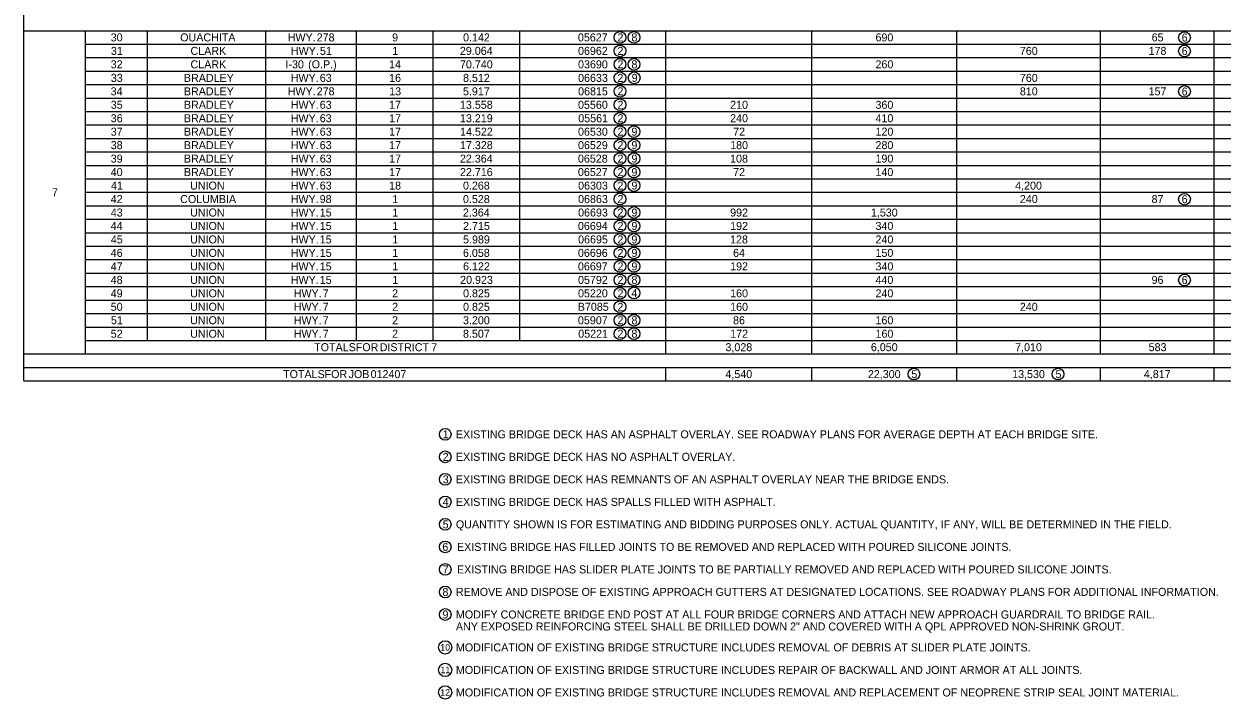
# Model space of a CAD drawing. Extents: x 16 to 1228740, y 11 to 152440.
# Drawn here: x 15.863 to 17.42, y 10.807 to 11.685 of the extents above; entities that cross this region are included whole.
import ezdxf

# ---------------------------------------------------------------- set-up
doc = ezdxf.new("R2010")
doc.units = 0
doc.layers.add('B_Text', color=7, linetype='Continuous')
doc.layers.add('Default', color=7, linetype='Continuous')

msp = doc.modelspace()

# ---------------------------------------------------------------- linework, layer by layer
at = {"layer": 'B_Text'}
for centre, radius in [((16.6381, 11.6677), 0.00762), ((16.6563, 11.6677), 0.00762), ((17.3717, 11.6675), 0.00762), ((16.6381, 11.6502), 0.00762), ((17.3717, 11.65), 0.00762), ((16.6381, 11.6327), 0.00762), ((16.6563, 11.6327), 0.00762), ((16.6381, 11.6151), 0.00762), ((16.6565, 11.6151), 0.00762), ((16.6381, 11.5976), 0.00762), ((17.3717, 11.5974), 0.00762), ((16.6381, 11.5801), 0.00762), ((16.6381, 11.5626), 0.00762), ((16.6381, 11.5451), 0.00762), ((16.6563, 11.5451), 0.00762), ((16.6381, 11.5276), 0.00762), ((16.6563, 11.5276), 0.00762), ((16.6381, 11.5101), 0.00762), ((16.6563, 11.5101), 0.00762), ((16.6381, 11.4926), 0.00762), ((16.6563, 11.4926), 0.00762), ((16.6381, 11.475), 0.00762), ((16.6563, 11.475), 0.00762), ((16.6381, 11.4575), 0.00762), ((17.3717, 11.4573), 0.00762), ((16.6381, 11.44), 0.00762), ((16.6563, 11.44), 0.00762), ((16.6381, 11.4225), 0.00762), ((16.6563, 11.4225), 0.00762), ((16.6381, 11.405), 0.00762), ((16.6563, 11.405), 0.00762), ((16.6381, 11.3875), 0.00762), ((16.6563, 11.3875), 0.00762), ((16.6381, 11.37), 0.00762), ((16.6563, 11.37), 0.00762), ((16.6381, 11.3524), 0.00762), ((16.6563, 11.3524), 0.00762), ((17.3717, 11.3522), 0.00762), ((16.6381, 11.3349), 0.00762), ((16.6563, 11.3353), 0.00762), ((16.6381, 11.3174), 0.00762), ((16.6381, 11.2999), 0.00762), ((16.6563, 11.2999), 0.00762), ((16.6381, 11.2824), 0.00762), ((16.6563, 11.2824), 0.00762), ((17.02, 11.2299), 0.00762), ((17.2073, 11.2299), 0.00762), ((16.4109, 11.1516), 0.00762), ((16.4109, 11.1223), 0.00762), ((16.4109, 11.093), 0.00762), ((16.4109, 11.0637), 0.00762), ((16.4109, 11.0345), 0.00762), ((16.4109, 11.0052), 0.00762), ((16.4109, 10.9759), 0.00762), ((16.4109, 10.9466), 0.00762), ((16.4109, 10.9173), 0.00762), ((16.4109, 10.8745), 0.0086), ((16.4109, 10.8452), 0.0086), ((16.4109, 10.816), 0.0086)]:
    msp.add_circle(centre, radius, dxfattribs=at)
at = {"layer": 'Default'}
for p, q in [((15.8634, 11.2211), (15.8634, 12.342)), ((15.8634, 11.6764), (17.9605, 11.6764)), ((15.9436, 11.2561), (15.9436, 11.6764)), ((16.0238, 11.2736), (16.0238, 11.6764)), ((16.1778, 11.2736), (16.1778, 11.6764)), ((16.2958, 11.2736), (16.2958, 11.6764)), ((16.3953, 11.2736), (16.3953, 11.6764)), ((16.5078, 11.2736), (16.5078, 11.6764)), ((16.6976, 11.2561), (16.6976, 11.6764)), ((16.8875, 11.2561), (16.8875, 11.6764)), ((17.0756, 11.2561), (17.0756, 11.6764)), ((17.2627, 11.2561), (17.2627, 11.6764)), ((17.4102, 11.2561), (17.4102, 11.6764)), ((15.9436, 11.6589), (17.9605, 11.6589)), ((16.8875, 11.6414), (16.8875, 11.6589)), ((17.0756, 11.6414), (17.0756, 11.6589)), ((15.9436, 11.6414), (17.9605, 11.6414)), ((16.8875, 11.6414), (17.0756, 11.6414)), ((17.0756, 11.6414), (17.9605, 11.6414)), ((15.9436, 11.6239), (17.9605, 11.6239)), ((15.9436, 11.6064), (17.9605, 11.6064)), ((15.9436, 11.5889), (17.9605, 11.5889)), ((15.9436, 11.5714), (17.9605, 11.5714)), ((15.9436, 11.5539), (17.9605, 11.5539)), ((15.9436, 11.5363), (17.9605, 11.5363)), ((15.9436, 11.5188), (17.9605, 11.5188)), ((15.9436, 11.5013), (17.9605, 11.5013)), ((15.9436, 11.4838), (17.9605, 11.4838)), ((15.9436, 11.4663), (17.9605, 11.4663)), ((15.9436, 11.4488), (17.9605, 11.4488)), ((15.9436, 11.4313), (17.9605, 11.4313)), ((15.9436, 11.4137), (17.9605, 11.4137)), ((15.9436, 11.3962), (17.9605, 11.3962)), ((15.9436, 11.3787), (17.9605, 11.3787)), ((15.9436, 11.3612), (17.9605, 11.3612)), ((15.9436, 11.3437), (17.9605, 11.3437)), ((15.9436, 11.3262), (17.9605, 11.3262)), ((15.9436, 11.3087), (17.9605, 11.3087)), ((15.9436, 11.2911), (17.9605, 11.2911)), ((15.9436, 11.2736), (17.9605, 11.2736)), ((15.8634, 11.2561), (17.9605, 11.2561)), ((15.8634, 11.2386), (17.9605, 11.2386)), ((16.6976, 11.2211), (16.6976, 11.2386)), ((16.8875, 11.2211), (16.8875, 11.2386)), ((17.0756, 11.2211), (17.0756, 11.2386)), ((17.2627, 11.2211), (17.2627, 11.2386)), ((17.4102, 11.2211), (17.4102, 11.2386)), ((15.8634, 11.2211), (17.9605, 11.2211))]:
    msp.add_line(p, q, dxfattribs=at)

# ---------------------------------------------------------------- texts
at = {"layer": 'B_Text'}
for s, height, p in [('2', 0.0104, (16.6348, 11.6625)), ('8', 0.0104, (16.6529, 11.6625)), ('6', 0.0104, (17.368, 11.6623)), ('2', 0.0104, (16.6348, 11.645)), ('6', 0.0104, (17.368, 11.6448)), ('2', 0.0104, (16.6348, 11.6275)), ('8', 0.0104, (16.6529, 11.6275)), ('2', 0.0104, (16.6348, 11.6099)), ('9', 0.0104, (16.6532, 11.6099)), ('2', 0.0104, (16.6348, 11.5924)), ('6', 0.0104, (17.368, 11.5922)), ('2', 0.0104, (16.6348, 11.5749)), ('2', 0.0104, (16.6348, 11.5574)), ('2', 0.0104, (16.6348, 11.5399)), ('9', 0.0104, (16.6529, 11.5399)), ('2', 0.0104, (16.6348, 11.5224)), ('9', 0.0104, (16.6529, 11.5224)), ('2', 0.0104, (16.6348, 11.5049)), ('9', 0.0104, (16.6529, 11.5049)), ('2', 0.0104, (16.6348, 11.4873)), ('9', 0.0104, (16.6529, 11.4873)), ('2', 0.0104, (16.6348, 11.4698)), ('9', 0.0104, (16.6529, 11.4698)), ('2', 0.0104, (16.6348, 11.4523)), ('6', 0.0104, (17.368, 11.4521)), ('2', 0.0104, (16.6348, 11.4348)), ('9', 0.0104, (16.6529, 11.4348)), ('2', 0.0104, (16.6348, 11.4173)), ('9', 0.0104, (16.6529, 11.4173)), ('2', 0.0104, (16.6348, 11.3998)), ('9', 0.0104, (16.6529, 11.3998)), ('2', 0.0104, (16.6348, 11.3823)), ('9', 0.0104, (16.6529, 11.3823)), ('2', 0.0104, (16.6348, 11.3648)), ('9', 0.0104, (16.6529, 11.3648)), ('2', 0.0104, (16.6348, 11.3472)), ('8', 0.0104, (16.6529, 11.3472)), ('6', 0.0104, (17.368, 11.347)), ('2', 0.0104, (16.6348, 11.3297)), ('4', 0.0104, (16.6529, 11.3301)), ('2', 0.0104, (16.6348, 11.3122)), ('2', 0.0104, (16.6348, 11.2947)), ('8', 0.0104, (16.6529, 11.2947)), ('2', 0.0104, (16.6348, 11.2772)), ('8', 0.0104, (16.6529, 11.2772)), ('5', 0.0104, (17.0167, 11.2246)), ('5', 0.0104, (17.204, 11.2246)), ('1', 0.0104, (16.4076, 11.1464)), ('EXISTING BRIDGE DECK HAS AN ASPHALT OVERLAY. SEE ROADWAY PLANS FOR AVERAGE DEPTH AT EACH BRIDGE SITE.', 0.0104167, (16.4248, 11.1464)), ('2', 0.0104, (16.4076, 11.1171)), ('EXISTING BRIDGE DECK HAS NO ASPHALT OVERLAY.', 0.010417, (16.4248, 11.1171)), ('3', 0.0104, (16.4076, 11.0878)), ('EXISTING BRIDGE DECK HAS REMNANTS OF AN ASPHALT OVERLAY NEAR THE BRIDGE ENDS.', 0.010417, (16.4248, 11.0878)), ('4', 0.0104, (16.4076, 11.0585)), ('EXISTING BRIDGE DECK HAS SPALLS FILLED WITH ASPHALT.', 0.010417, (16.4248, 11.0585)), ('5', 0.0104, (16.4076, 11.0293)), ('QUANTITY SHOWN IS FOR ESTIMATING AND BIDDING PURPOSES ONLY. ACTUAL QUANTITY, IF ANY, WILL BE DETERMINED IN THE FIELD.', 0.0104167, (16.4248, 11.0293)), ('6', 0.0104, (16.4072, 11)), ('EXISTING BRIDGE HAS FILLED JOINTS TO BE REMOVED AND REPLACED WITH POURED SILICONE JOINTS.', 0.010417, (16.4262, 11)), ('7', 0.0104, (16.4076, 10.9707)), ('EXISTING BRIDGE HAS SLIDER PLATE JOINTS TO BE PARTIALLY REMOVED AND REPLACED WITH POURED SILICONE JOINTS.', 0.0104167, (16.4262, 10.9707)), ('8', 0.0104, (16.4073, 10.9414)), ('REMOVE AND DISPOSE OF EXISTING APPROACH GUTTERS AT DESIGNATED LOCATIONS. SEE ROADWAY PLANS FOR ADDITIONAL INFORMATION.', 0.0104167, (16.4248, 10.9415)), ('9', 0.0104, (16.4073, 10.9121)), ('MODIFY CONCRETE BRIDGE END POST AT ALL FOUR BRIDGE CORNERS AND ATTACH NEW APPROACH GUARDRAIL TO BRIDGE RAIL. ', 0.0104167, (16.4248, 10.9121)), ('ANY EXPOSED REINFORCING STEEL SHALL BE DRILLED DOWN 2" AND COVERED WITH A QPL APPROVED NON-SHRINK GROUT.', 0.0104167, (16.4248, 10.8965)), ('10', 0.0085, (16.4045, 10.8703)), ('MODIFICATION OF EXISTING BRIDGE STRUCTURE INCLUDES REMOVAL OF DEBRIS AT SLIDER PLATE JOINTS.', 0.010417, (16.4248, 10.8693)), ('11', 0.0085, (16.4048, 10.841)), ('MODIFICATION OF EXISTING BRIDGE STRUCTURE INCLUDES REPAIR OF BACKWALL AND JOINT ARMOR AT ALL JOINTS.', 0.010417, (16.4248, 10.84)), ('12', 0.0085, (16.4045, 10.8117)), ('MODIFICATION OF EXISTING BRIDGE STRUCTURE INCLUDES REMOVAL AND REPLACEMENT OF NEOPRENE STRIP SEAL JOINT MATERIAL.', 0.0104167, (16.4248, 10.8107))]:
    msp.add_text(s, height=height, dxfattribs=at).set_placement(p)
at = {"layer": 'Default'}
for s, p in [('30', (15.9762, 11.6625)), ('OUACHITA', (16.0665, 11.6625)), ('HWY.', (16.2062, 11.6625)), (' 278', (16.24, 11.6625)), ('9', (16.3419, 11.6625)), ('0.142', (16.4341, 11.6625)), ('05627', (16.5834, 11.6625)), ('690', (16.9701, 11.6625)), ('65', (17.329, 11.6625)), ('31', (15.9765, 11.645)), ('CLARK', (16.0799, 11.645)), ('HWY.', (16.2104, 11.645)), (' 51', (16.2442, 11.645)), ('1', (16.3422, 11.645)), ('29.064', (16.43, 11.645)), ('06962', (16.5835, 11.645)), ('760', (17.1577, 11.645)), ('178', (17.325, 11.645)), ('32', (15.9762, 11.6275)), ('CLARK', (16.0799, 11.6275)), ('I-30', (16.2033, 11.6275)), (' (O.P.)', (16.2289, 11.6275)), ('14', (16.3379, 11.6275)), ('70.740', (16.4301, 11.6275)), ('03690', (16.5835, 11.6275)), ('260', (16.9701, 11.6275)), ('33', (15.9763, 11.6099)), ('BRADLEY', (16.0713, 11.6099)), ('HWY.', (16.2102, 11.6099)), (' 63', (16.244, 11.6099)), ('16', (16.338, 11.6099)), ('8.512', (16.4341, 11.6099)), ('06633', (16.5836, 11.6099)), ('760', (17.1577, 11.6099)), ('34', (15.9761, 11.5924)), ('BRADLEY', (16.0713, 11.5924)), ('HWY.', (16.2062, 11.5924)), (' 278', (16.24, 11.5924)), ('13', (16.3381, 11.5924)), ('5.917', (16.434, 11.5924)), ('06815', (16.5836, 11.5924)), ('810', (17.1577, 11.5924)), ('157', (17.325, 11.5924)), ('35', (15.9763, 11.5749)), ('BRADLEY', (16.0713, 11.5749)), ('HWY.', (16.2102, 11.5749)), (' 63', (16.244, 11.5749)), ('17', (16.338, 11.5749)), ('13.558', (16.4301, 11.5749)), ('05560', (16.5835, 11.5749)), ('210', (16.7812, 11.5749)), ('360', (16.9701, 11.5749)), ('36', (15.9762, 11.5574)), ('BRADLEY', (16.0713, 11.5574)), ('HWY.', (16.2102, 11.5574)), (' 63', (16.244, 11.5574)), ('17', (16.338, 11.5574)), ('13.219', (16.4301, 11.5574)), ('05561', (16.5838, 11.5574)), ('240', (16.7812, 11.5574)), ('410', (16.9701, 11.5574)), ('37', (15.9762, 11.5399)), ('BRADLEY', (16.0713, 11.5399)), ('HWY.', (16.2102, 11.5399)), (' 63', (16.244, 11.5399)), ('17', (16.338, 11.5399)), ('14.522', (16.4302, 11.5399)), ('06530', (16.5835, 11.5399)), ('72', (16.7851, 11.5399)), ('120', (16.9701, 11.5399)), ('38', (15.9762, 11.5224)), ('BRADLEY', (16.0713, 11.5224)), ('HWY.', (16.2102, 11.5224)), (' 63', (16.244, 11.5224)), ('17', (16.338, 11.5224)), ('17.328', (16.4301, 11.5224)), ('06529', (16.5835, 11.5224)), ('180', (16.7812, 11.5224)), ('280', (16.9701, 11.5224)), ('39', (15.9762, 11.5049)), ('BRADLEY', (16.0713, 11.5049)), ('HWY.', (16.2102, 11.5049)), (' 63', (16.244, 11.5049)), ('17', (16.338, 11.5049)), ('22.364', (16.43, 11.5049)), ('06528', (16.5834, 11.5049)), ('108', (16.7811, 11.5049)), ('190', (16.9701, 11.5049)), ('40', (15.9762, 11.4874)), ('BRADLEY', (16.0713, 11.4874)), ('HWY.', (16.2102, 11.4874)), (' 63', (16.244, 11.4874)), ('17', (16.338, 11.4874)), ('22.716', (16.4301, 11.4874)), ('06527', (16.5834, 11.4874)), ('72', (16.7851, 11.4874)), ('140', (16.9701, 11.4874)), ('41', (15.9765, 11.4698)), ('UNION', (16.0794, 11.4698)), ('HWY.', (16.2102, 11.4698)), (' 63', (16.244, 11.4698)), ('18', (16.338, 11.4698)), ('0.268', (16.434, 11.4698)), ('06303', (16.5836, 11.4698)), ('4,200', (17.1516, 11.4698)), ('7', (15.8999, 11.4611)), ('42', (15.9762, 11.4523)), ('COLUMBIA', (16.0665, 11.4523)), ('HWY.', (16.2101, 11.4523)), (' 98', (16.2439, 11.4523)), ('1', (16.3422, 11.4523)), ('0.528', (16.434, 11.4523)), ('06863', (16.5836, 11.4523)), ('240', (17.1577, 11.4523)), ('87', (17.3289, 11.4523)), ('43', (15.9763, 11.4348)), ('UNION', (16.0794, 11.4348)), ('HWY.', (16.2102, 11.4348)), (' 15', (16.244, 11.4348)), ('1', (16.3422, 11.4348)), ('2.364', (16.4339, 11.4348)), ('06693', (16.5836, 11.4348)), ('992', (16.7812, 11.4348)), ('1,530', (16.9641, 11.4348)), ('44', (15.9761, 11.4173)), ('UNION', (16.0794, 11.4173)), ('HWY.', (16.2102, 11.4173)), (' 15', (16.244, 11.4173)), ('1', (16.3422, 11.4173)), ('2.715', (16.4341, 11.4173)), ('06694', (16.5834, 11.4173)), ('192', (16.7812, 11.4173)), ('340', (16.9701, 11.4173)), ('45', (15.9763, 11.3998)), ('UNION', (16.0794, 11.3998)), ('HWY.', (16.2102, 11.3998)), (' 15', (16.244, 11.3998)), ('1', (16.3422, 11.3998)), ('5.989', (16.4341, 11.3998)), ('06695', (16.5836, 11.3998)), ('128', (16.7811, 11.3998)), ('240', (16.9701, 11.3998)), ('46', (15.9762, 11.3823)), ('UNION', (16.0794, 11.3823)), ('HWY.', (16.2102, 11.3823)), (' 15', (16.244, 11.3823)), ('1', (16.3422, 11.3823)), ('6.058', (16.434, 11.3823)), ('06696', (16.5834, 11.3823)), ('64', (16.785, 11.3823)), ('150', (16.9701, 11.3823)), ('47', (15.9762, 11.3648)), ('UNION', (16.0794, 11.3648)), ('HWY.', (16.2102, 11.3648)), (' 15', (16.244, 11.3648)), ('1', (16.3422, 11.3648)), ('6.122', (16.4341, 11.3648)), ('06697', (16.5834, 11.3648)), ('192', (16.7812, 11.3648)), ('340', (16.9701, 11.3648)), ('48', (15.9762, 11.3472)), ('UNION', (16.0794, 11.3472)), ('HWY.', (16.2102, 11.3472)), (' 15', (16.244, 11.3472)), ('1', (16.3422, 11.3472)), ('20.923', (16.4303, 11.3472)), ('05792', (16.5835, 11.3472)), ('440', (16.9701, 11.3472)), ('96', (17.3289, 11.3472)), ('49', (15.9762, 11.3297)), ('UNION', (16.0794, 11.3297)), ('HWY.', (16.214, 11.3297)), (' 7', (16.2478, 11.3297)), ('2', (16.3419, 11.3297)), ('0.825', (16.4341, 11.3297)), ('05220', (16.5835, 11.3297)), ('160', (16.7812, 11.3297)), ('240', (16.9701, 11.3297)), ('50', (15.9762, 11.3122)), ('UNION', (16.0794, 11.3122)), ('HWY.', (16.214, 11.3122)), (' 7', (16.2478, 11.3122)), ('2', (16.3419, 11.3122)), ('0.825', (16.4341, 11.3122)), ('B7085', (16.5832, 11.3122)), ('160', (16.7812, 11.3122)), ('240', (17.1577, 11.3122)), ('51', (15.9765, 11.2947)), ('UNION', (16.0794, 11.2947)), ('HWY.', (16.214, 11.2947)), (' 7', (16.2478, 11.2947)), ('2', (16.3419, 11.2947)), ('3.200', (16.434, 11.2947)), ('05907', (16.5834, 11.2947)), ('86', (16.785, 11.2947)), ('160', (16.9701, 11.2947)), ('52', (15.9762, 11.2772)), ('UNION', (16.0794, 11.2772)), ('HWY.', (16.214, 11.2772)), (' 7', (16.2478, 11.2772)), ('2', (16.3419, 11.2772)), ('8.507', (16.434, 11.2772)), ('05221', (16.5838, 11.2772)), ('172', (16.7812, 11.2772)), ('160', (16.9701, 11.2772)), ('TOTALS', (16.2406, 11.2597)), (' FOR', (16.2908, 11.2597)), (' DISTRICT', (16.3219, 11.2597)), (' 7', (16.3889, 11.2597)), ('3,028', (16.7751, 11.2597)), ('6,050', (16.9641, 11.2597)), ('7,010', (17.1516, 11.2597)), ('583', (17.3251, 11.2597)), ('TOTALS', (16.2002, 11.2247)), (' FOR', (16.2503, 11.2247)), (' JOB', (16.2815, 11.2247)), (' 012407', (16.3101, 11.2247)), ('4,540', (16.7751, 11.2247)), ('22,300', (16.9602, 11.2247)), ('13,530', (17.1477, 11.2247)), ('4,817', (17.3189, 11.2247))]:
    msp.add_text(s, height=0.0104, dxfattribs=at).set_placement(p)

doc.saveas('drawing.dxf')
